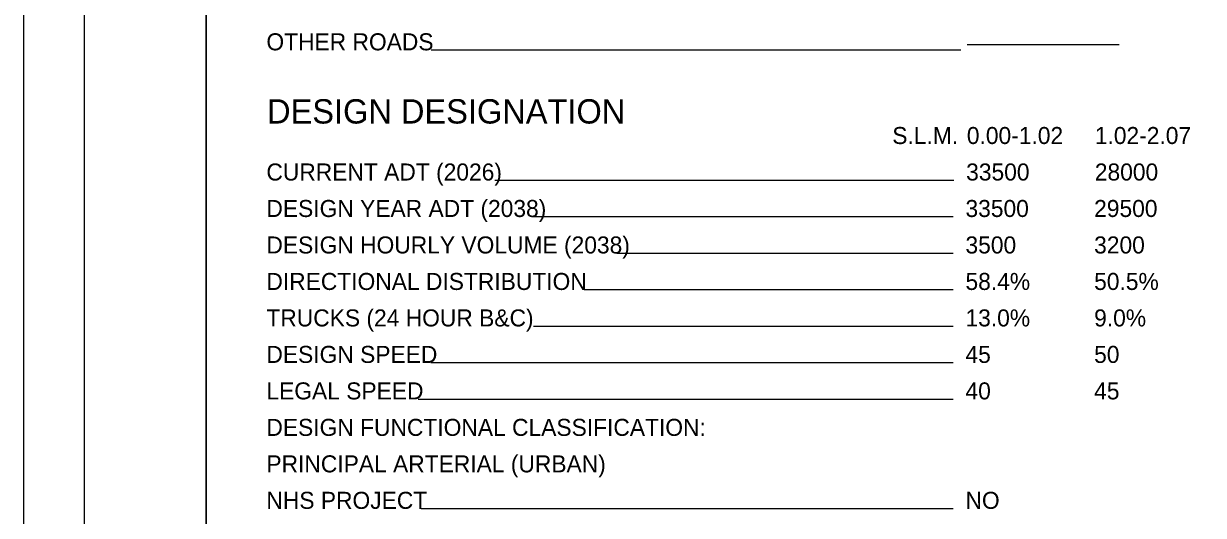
# Model space of a CAD drawing. Extents: x 0 to 34, y 0 to 22.
# Drawn here: x 0 to 9.69, y 7.05 to 11.1 of the extents above; entities that cross this region are included whole.
import ezdxf

# ---------------------------------------------------------------- set-up
doc = ezdxf.new("R2010")
doc.units = 0
for name, color, linetype in [('SH_Border', 7, 'Continuous'), ('SH_Cut_Line', 7, 'Continuous'), ('SH_Data', 7, 'Continuous'), ('SH_Text', 7, 'Continuous')]:
    doc.layers.add(name, color=color, linetype=linetype)

msp = doc.modelspace()

# ---------------------------------------------------------------- linework, layer by layer
at = {"layer": 'SH_Border'}
for points in [[(0.5, 21.5), (1.5, 21.5), (1.5, 0.5), (0.5, 0.5)], [(1.5, 21.5), (33.5, 21.5), (33.5, 0.5), (1.5, 0.5)]]:
    msp.add_lwpolyline(points, close=True, dxfattribs=at)
at = {"layer": 'SH_Cut_Line'}
msp.add_lwpolyline([(0, 0), (34, 0), (34, 22), (0, 22)], close=True, dxfattribs=at)
at = {"layer": 'SH_Data'}
for p, q in [((7.7, 10.8767), (3.3471, 10.8767)), ((9, 10.9223), (7.75, 10.9223)), ((7.6424, 9.8062), (3.871, 9.8062)), ((7.6368, 9.5062), (4.1885, 9.5062)), ((7.6368, 9.2062), (4.8723, 9.2062)), ((7.6368, 8.9062), (4.6037, 8.9062)), ((7.6368, 8.6062), (4.1885, 8.6062)), ((7.6368, 8.3062), (3.346, 8.3062)), ((7.6368, 8.0062), (3.2422, 8.0062)), ((7.6368, 7.1062), (3.2669, 7.1062))]:
    msp.add_line(p, q, dxfattribs=at)

# ---------------------------------------------------------------- texts
msp.add_text('DESIGN DESIGNATION', height=0.2, dxfattribs=at).set_placement((2, 10.2747))
at = {"layer": 'SH_Text'}
for s, p in [('OTHER ROADS', (1.9944, 10.8767)), ('S.L.M.', (7.1357, 10.1062)), ('0.00-1.02', (7.748, 10.1062)), ('1.02-2.07', (8.7992, 10.1062)), ('CURRENT ADT (2026)', (1.9944, 9.8062)), ('33500', (7.7424, 9.8062)), ('28000', (8.7992, 9.8062)), ('DESIGN YEAR ADT (2038)', (1.9944, 9.5062)), ('33500', (7.7368, 9.5062)), ('29500', (8.7936, 9.5062)), ('DESIGN HOURLY VOLUME (2038)', (1.9944, 9.2062)), ('3500', (7.7368, 9.2062)), ('3200', (8.7936, 9.2062)), ('DIRECTIONAL DISTRIBUTION', (1.9944, 8.9062)), ('58.4%', (7.7368, 8.9062)), ('50.5%', (8.7936, 8.9062)), ('TRUCKS (24 HOUR B&C)', (1.9944, 8.6062)), ('13.0%', (7.7368, 8.6062)), ('9.0%', (8.7936, 8.6062)), ('DESIGN SPEED', (1.9944, 8.3062)), ('45', (7.7368, 8.3062)), ('50', (8.7936, 8.3062)), ('LEGAL SPEED', (1.9944, 8.0062)), ('40', (7.7368, 8.0062)), ('45', (8.7936, 8.0062)), ('DESIGN FUNCTIONAL CLASSIFICATION:', (1.9944, 7.7062)), ('PRINCIPAL ARTERIAL (URBAN)', (1.9944, 7.4062)), ('NHS PROJECT', (1.9944, 7.1062)), ('NO', (7.7368, 7.1062))]:
    msp.add_text(s, height=0.14, dxfattribs=at).set_placement(p)

doc.saveas('drawing.dxf')
